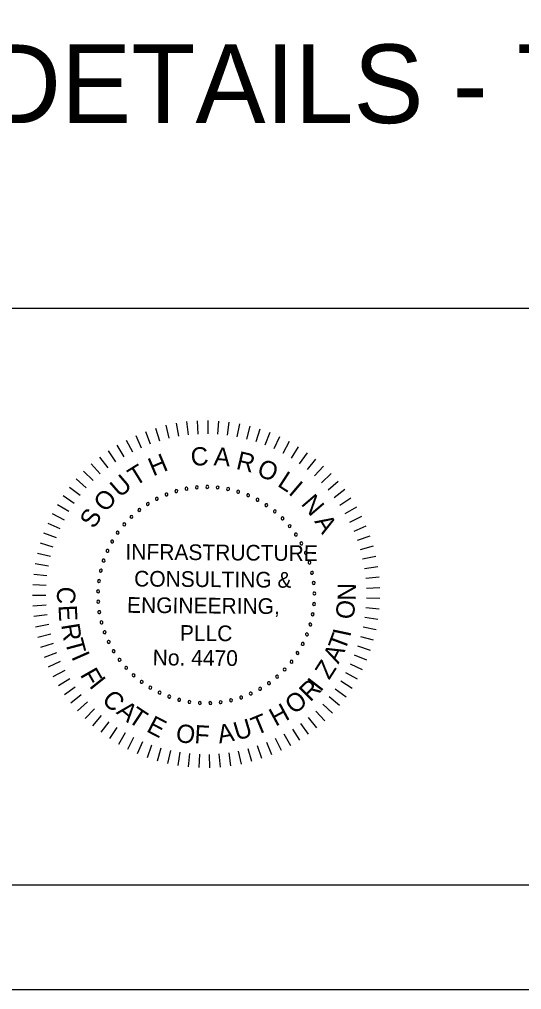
# Model space of a CAD drawing. Extents: x -125.5 to -89.4, y -5.1 to 16.9.
# Drawn here: x -100.09 to -97.697, y -5.066 to -0.44 of the extents above; entities that cross this region are included whole.
import ezdxf

# ---------------------------------------------------------------- set-up
doc = ezdxf.new("R2010")
doc.units = 0
for name, color, linetype in [('BR_BORDER LINES', 7, 'Continuous'), ('BR_TEXT', 7, 'Continuous'), ('Level 31', 7, 'Continuous')]:
    doc.layers.add(name, color=color, linetype=linetype)

msp = doc.modelspace()

# ---------------------------------------------------------------- linework, layer by layer
at = {"layer": 'BR_BORDER LINES'}
for p, q in [((-102.8989, -1.8161), (-97.5337, -1.8161)), ((-123.6994, -4.5662), (-90.0334, -4.5662))]:
    msp.add_line(p, q, dxfattribs=at)
at = {"layer": 'BR_TEXT'}
for p, q in [((-99.2931, -2.3579), (-99.2858, -2.4212)), ((-99.2427, -2.3538), (-99.2394, -2.4174)), ((-99.1923, -2.3527), (-99.1928, -2.4164)), ((-99.1418, -2.3548), (-99.1462, -2.4183)), ((-99.489, -2.4048), (-99.4667, -2.4644)), ((-99.4412, -2.3886), (-99.4226, -2.4495)), ((-99.3925, -2.3754), (-99.3776, -2.4373)), ((-99.343, -2.3651), (-99.332, -2.4278)), ((-99.0916, -2.3599), (-99.0999, -2.423)), ((-99.0418, -2.368), (-99.0539, -2.4305)), ((-98.9925, -2.3792), (-99.0084, -2.4408)), ((-98.9441, -2.3933), (-98.9637, -2.4539)), ((-99.5813, -2.4457), (-99.5519, -2.5022)), ((-99.5358, -2.4238), (-99.5099, -2.482)), ((-98.8966, -2.4104), (-98.9199, -2.4696)), ((-98.8502, -2.4303), (-98.877, -2.488)), ((-99.6678, -2.4975), (-99.6318, -2.55)), ((-99.6253, -2.4703), (-99.5926, -2.5249)), ((-98.8051, -2.453), (-98.8354, -2.509)), ((-98.7615, -2.4785), (-98.7952, -2.5325)), ((-99.7086, -2.5273), (-99.6694, -2.5775)), ((-98.7195, -2.5065), (-98.7564, -2.5584)), ((-98.6793, -2.5371), (-98.7193, -2.5866)), ((-99.7475, -2.5595), (-99.7053, -2.6072)), ((-98.6411, -2.57), (-98.684, -2.617)), ((-99.819, -2.6308), (-99.7713, -2.673)), ((-99.7843, -2.5941), (-99.7393, -2.6391)), ((-98.6049, -2.6052), (-98.6506, -2.6495)), ((-99.8513, -2.6695), (-99.8012, -2.7087)), ((-98.571, -2.6426), (-98.6193, -2.684)), ((-98.5393, -2.6819), (-98.5901, -2.7204)), ((-99.8813, -2.7102), (-99.8288, -2.7463)), ((-98.5102, -2.7232), (-98.5632, -2.7584)), ((-99.9087, -2.7526), (-99.8541, -2.7854)), ((-98.4836, -2.7661), (-98.5387, -2.798)), ((-99.9334, -2.7965), (-99.877, -2.826)), ((-98.4597, -2.8105), (-98.5166, -2.839)), ((-99.9555, -2.842), (-99.8973, -2.8679)), ((-98.4385, -2.8563), (-98.497, -2.8813)), ((-99.9747, -2.8886), (-99.9151, -2.911)), ((-98.4202, -2.9034), (-98.4801, -2.9248)), ((-99.991, -2.9364), (-99.9302, -2.9551)), ((-98.4047, -2.9514), (-98.4659, -2.9691)), ((-100.0044, -2.9851), (-99.9426, -3)), ((-98.3922, -3.0004), (-98.4544, -3.0143)), ((-100.0149, -3.0345), (-99.9522, -3.0456)), ((-98.3828, -3.05), (-98.4456, -3.0601)), ((-100.0222, -3.0844), (-99.959, -3.0917)), ((-100.0266, -3.1347), (-99.963, -3.1382)), ((-98.3763, -3.1), (-98.4397, -3.1063)), ((-100.0278, -3.1852), (-99.9641, -3.1847)), ((-98.373, -3.1504), (-98.4366, -3.1528)), ((-100.026, -3.2356), (-99.9625, -3.2313)), ((-98.3727, -3.2009), (-98.4363, -3.1994)), ((-100.0211, -3.2859), (-99.9579, -3.2777)), ((-98.3755, -3.2513), (-98.4389, -3.2459)), ((-100.0131, -3.3357), (-99.9506, -3.3237)), ((-98.3813, -3.3014), (-98.4443, -3.2922)), ((-100.0021, -3.385), (-99.9405, -3.3692)), ((-98.3902, -3.3511), (-98.4525, -3.3381)), ((-99.9882, -3.4335), (-99.9276, -3.414)), ((-98.4021, -3.4002), (-98.4635, -3.3834)), ((-99.9713, -3.4811), (-99.912, -3.4579)), ((-98.417, -3.4484), (-98.4773, -3.4279)), ((-99.9515, -3.5276), (-99.8937, -3.5008)), ((-98.4554, -3.5417), (-98.5128, -3.514)), ((-98.4348, -3.4957), (-98.4937, -3.4715)), ((-99.929, -3.5727), (-99.8729, -3.5425)), ((-98.4789, -3.5865), (-98.5344, -3.5553)), ((-99.9037, -3.6164), (-99.8496, -3.5828)), ((-98.505, -3.6297), (-98.5585, -3.5952)), ((-99.8758, -3.6585), (-99.8239, -3.6217)), ((-98.5336, -3.6712), (-98.5849, -3.6335)), ((-99.8454, -3.6988), (-99.7958, -3.6589)), ((-99.8126, -3.7372), (-99.7655, -3.6943)), ((-98.5648, -3.7109), (-98.6137, -3.6702)), ((-99.7775, -3.7735), (-99.7331, -3.7278)), ((-98.6341, -3.7843), (-98.6777, -3.7379)), ((-98.5983, -3.7487), (-98.6447, -3.705)), ((-99.7403, -3.8076), (-99.6988, -3.7593)), ((-99.701, -3.8393), (-99.6626, -3.7886)), ((-98.672, -3.8177), (-98.7126, -3.7687)), ((-99.6599, -3.8687), (-99.6246, -3.8157)), ((-98.7534, -3.8772), (-98.7879, -3.8237)), ((-98.7118, -3.8487), (-98.7494, -3.7974)), ((-99.6171, -3.8954), (-99.5851, -3.8404)), ((-99.5728, -3.9195), (-99.5442, -3.8626)), ((-99.527, -3.9408), (-99.5019, -3.8823)), ((-98.8416, -3.9264), (-98.8692, -3.8691)), ((-98.7967, -3.9032), (-98.8278, -3.8476)), ((-99.48, -3.9594), (-99.4586, -3.8994)), ((-99.432, -3.975), (-99.4143, -3.9138)), ((-99.3832, -3.9876), (-99.3692, -3.9255)), ((-99.0324, -3.991), (-99.0454, -3.9286)), ((-98.9833, -3.9792), (-99.0001, -3.9178)), ((-98.935, -3.9645), (-98.9555, -3.9042)), ((-98.8877, -3.9469), (-98.9118, -3.888)), ((-99.3336, -3.9973), (-99.3234, -3.9344)), ((-99.2836, -4.0039), (-99.2772, -3.9406)), ((-99.2332, -4.0075), (-99.2307, -3.9438)), ((-99.1827, -4.0079), (-99.1841, -3.9443)), ((-99.1323, -4.0053), (-99.1376, -3.9419)), ((-99.0821, -3.9997), (-99.0913, -3.9367))]:
    msp.add_line(p, q, dxfattribs=at)
for centre, start, end in [((-99.3424, -2.6889), 16.1422, 196.1422), ((-99.2939, -2.6775), 10.6038, 190.6038), ((-99.2939, -2.6775), 190.6038, 10.6038), ((-99.2445, -2.6708), 5.0653, 185.0653), ((-99.2445, -2.6708), 185.0653, 5.0653), ((-99.1947, -2.6689), 359.5268, 179.5268), ((-99.1947, -2.6689), 179.5268, 359.5268), ((-99.145, -2.6718), 173.9884, 353.9884), ((-99.145, -2.6718), 353.9884, 173.9884), ((-99.0957, -2.6795), 168.4499, 348.4499), ((-99.0957, -2.6795), 348.4499, 168.4499), ((-99.435, -2.7255), 27.2191, 207.2191), ((-99.435, -2.7255), 207.2191, 27.2191), ((-99.3896, -2.705), 21.6807, 201.6807), ((-99.3896, -2.705), 201.6807, 21.6807), ((-99.3424, -2.6889), 196.1422, 16.1422), ((-99.0475, -2.6919), 162.9114, 342.9114), ((-99.0475, -2.6919), 342.9114, 162.9114), ((-99.0006, -2.709), 157.373, 337.373), ((-99.0006, -2.709), 337.373, 157.373), ((-98.9557, -2.7304), 151.8345, 331.8345), ((-98.9557, -2.7304), 331.8345, 151.8345), ((-99.5188, -2.7792), 38.2961, 218.2961), ((-99.5188, -2.7792), 218.2961, 38.2961), ((-99.4782, -2.7503), 32.7576, 212.7576), ((-99.4782, -2.7503), 212.7576, 32.7576), ((-98.913, -2.7561), 146.2961, 326.2961), ((-98.913, -2.7561), 326.2961, 146.2961), ((-99.5564, -2.8119), 43.8345, 223.8345), ((-99.5564, -2.8119), 223.8345, 43.8345), ((-98.873, -2.7858), 140.7576, 320.7576), ((-98.873, -2.7858), 320.7576, 140.7576), ((-98.836, -2.8192), 135.2191, 315.2191), ((-98.836, -2.8192), 315.2191, 135.2191), ((-99.5907, -2.848), 49.373, 229.373), ((-99.5907, -2.848), 229.373, 49.373), ((-98.8024, -2.8561), 129.6807, 309.6807), ((-98.8024, -2.8561), 309.6807, 129.6807), ((-99.6214, -2.8873), 54.9114, 234.9114), ((-99.6214, -2.8873), 234.9114, 54.9114), ((-98.7726, -2.896), 124.1422, 304.1422), ((-98.7726, -2.896), 304.1422, 124.1422), ((-99.6481, -2.9293), 60.4499, 240.4499), ((-99.6481, -2.9293), 240.4499, 60.4499), ((-98.7467, -2.9386), 118.6038, 298.6038), ((-98.7467, -2.9386), 298.6038, 118.6038), ((-99.6706, -2.9738), 65.9884, 245.9884), ((-99.6706, -2.9738), 245.9884, 65.9884), ((-98.7251, -2.9835), 113.0653, 293.0653), ((-98.7251, -2.9835), 293.0653, 113.0653), ((-99.6888, -3.0202), 71.5268, 251.5268), ((-99.6888, -3.0202), 251.5268, 71.5268), ((-98.7079, -3.0302), 107.5268, 287.5268), ((-98.7079, -3.0302), 287.5268, 107.5268), ((-99.7024, -3.0681), 77.0653, 257.0653), ((-99.7024, -3.0681), 257.0653, 77.0653), ((-98.6953, -3.0785), 101.9884, 281.9884), ((-98.6953, -3.0785), 281.9884, 101.9884), ((-99.7113, -3.1172), 82.6038, 262.6038), ((-99.7113, -3.1172), 262.6038, 82.6038), ((-98.6874, -3.1277), 96.4499, 276.4499), ((-98.6874, -3.1277), 276.4499, 96.4499), ((-99.7154, -3.1668), 88.1422, 268.1422), ((-99.7154, -3.1668), 268.1422, 88.1422), ((-98.6843, -3.1774), 90.9114, 270.9114), ((-98.6843, -3.1774), 270.9114, 90.9114), ((-99.7147, -3.2167), 93.6807, 273.6807), ((-99.7147, -3.2167), 273.6807, 93.6807), ((-98.686, -3.2272), 85.373, 265.373), ((-98.686, -3.2272), 265.373, 85.373), ((-99.7092, -3.2662), 99.2191, 279.2191), ((-99.7092, -3.2662), 279.2191, 99.2191), ((-98.6926, -3.2766), 79.8345, 259.8345), ((-98.6926, -3.2766), 259.8345, 79.8345), ((-99.6989, -3.3149), 104.7576, 284.7576), ((-99.6989, -3.3149), 284.7576, 104.7576), ((-98.7038, -3.3251), 74.2961, 254.2961), ((-98.7038, -3.3251), 254.2961, 74.2961), ((-99.684, -3.3625), 110.2961, 290.2961), ((-99.684, -3.3625), 290.2961, 110.2961), ((-98.7197, -3.3724), 68.7576, 248.7576), ((-98.7197, -3.3724), 248.7576, 68.7576), ((-99.6646, -3.4084), 115.8345, 295.8345), ((-99.6646, -3.4084), 295.8345, 115.8345), ((-98.7401, -3.4178), 63.2191, 243.2191), ((-98.7401, -3.4178), 243.2191, 63.2191), ((-99.6408, -3.4522), 121.373, 301.373), ((-99.6408, -3.4522), 301.373, 121.373), ((-98.7647, -3.4611), 57.6807, 237.6807), ((-98.7647, -3.4611), 237.6807, 57.6807), ((-99.6129, -3.4935), 126.9114, 306.9114), ((-99.6129, -3.4935), 306.9114, 126.9114), ((-98.7934, -3.5019), 52.1422, 232.1422), ((-98.7934, -3.5019), 232.1422, 52.1422), ((-99.5812, -3.5319), 132.4499, 312.4499), ((-99.5812, -3.5319), 312.4499, 132.4499), ((-99.5459, -3.5671), 317.9884, 137.9884), ((-98.826, -3.5396), 46.6038, 226.6038), ((-98.826, -3.5396), 226.6038, 46.6038), ((-99.5459, -3.5671), 137.9884, 317.9884), ((-99.5074, -3.5987), 143.5268, 323.5268), ((-99.5074, -3.5987), 323.5268, 143.5268), ((-98.9012, -3.6049), 35.5268, 215.5268), ((-98.9012, -3.6049), 215.5268, 35.5268), ((-98.862, -3.5741), 41.0653, 221.0653), ((-98.862, -3.5741), 221.0653, 41.0653), ((-99.466, -3.6264), 149.0653, 329.0653), ((-99.466, -3.6264), 329.0653, 149.0653), ((-99.4221, -3.65), 154.6038, 334.6038), ((-99.4221, -3.65), 334.6038, 154.6038), ((-98.9875, -3.6545), 24.4499, 204.4499), ((-98.9875, -3.6545), 204.4499, 24.4499), ((-98.9431, -3.6317), 29.9884, 209.9884), ((-98.9431, -3.6317), 209.9884, 29.9884), ((-99.3761, -3.6693), 160.1422, 340.1422), ((-99.3761, -3.6693), 340.1422, 160.1422), ((-99.3285, -3.684), 165.6807, 345.6807), ((-99.3285, -3.684), 345.6807, 165.6807), ((-99.2797, -3.6941), 351.2191, 171.2191), ((-99.2797, -3.6941), 171.2191, 351.2191), ((-99.2302, -3.6994), 356.7576, 176.7576), ((-99.2302, -3.6994), 176.7576, 356.7576), ((-99.1803, -3.6999), 2.2961, 182.2961), ((-99.1803, -3.6999), 182.2961, 2.2961), ((-99.1307, -3.6956), 7.8345, 187.8345), ((-99.1307, -3.6956), 187.8345, 7.8345), ((-99.0817, -3.6865), 13.373, 193.373), ((-99.0817, -3.6865), 193.373, 13.373), ((-99.0338, -3.6728), 18.9114, 198.9114), ((-99.0338, -3.6728), 198.9114, 18.9114)]:
    msp.add_arc(centre, 0.00701, start, end, dxfattribs=at)
at = {"layer": 'Level 31'}
msp.add_lwpolyline([(-125.5328, -5.0661), (-89.5328, -5.0661), (-89.5328, 16.9339), (-125.5328, 16.9339)], close=True, dxfattribs=at)

# ---------------------------------------------------------------- texts
at = {"layer": 'BR_TEXT'}
msp.add_text('BEARING PAD DETAILS - TYPE 2', height=0.375, dxfattribs=at).set_placement((-103.821, -0.9342))
for s, height, rotation, p in [('C', 0.0872, 4.7281, (-99.2702, -2.5703)), ('A', 0.0872, 355.6981, (-99.1657, -2.5654)), ('H', 0.0872, 22.7882, (-99.453, -2.6197)), ('R', 0.0872, 346.6681, (-99.0615, -2.5824)), ('O', 0.0872, 337.638, (-98.9637, -2.6122)), ('T', 0.0872, 31.8182, (-99.5379, -2.6674)), ('U', 0.0872, 40.8482, (-99.6112, -2.7235)), ('L', 0.0872, 327.108, (-98.8649, -2.6626)), ('I', 0.0872, 319.578, (-98.8123, -2.7005)), ('O', 0.0872, 49.8782, (-99.6782, -2.7945)), ('N', 0.0872, 310.548, (-98.7515, -2.7512)), ('S', 0.0872, 58.9083, (-99.7336, -2.8727)), ('A', 0.0872, 301.5179, (-98.6864, -2.8336)), ('INFRASTRUCTURE', 0.074771, 359.5268, (-99.585, -3.0152)), ('CONSULTING &', 0.074771, 359.5268, (-99.5437, -3.1438)), ('N', 0.0872, 89.2085, (-98.4872, -3.2124)), ('C', 0.0872, 267.025, (-99.9086, -3.1426)), ('ENGINEERING,', 0.074771, 359.5268, (-99.5773, -3.2693)), ('O', 0.0872, 83.2085, (-98.4982, -3.3038)), ('E', 0.0872, 273.025, (-99.9042, -3.2342)), ('R', 0.0872, 279.025, (-99.8914, -3.3265)), ('PLLC', 0.07477, 359.5268, (-99.3256, -3.4028)), ('T', 0.0872, 69.3954, (-98.5394, -3.4556)), ('I', 0.0872, 77.9093, (-98.5137, -3.3881)), ('T', 0.0872, 285.025, (-99.874, -3.4053)), ('I', 0.0872, 293.7713, (-99.8443, -3.4784)), ('No. 4470', 0.07477, 359.5268, (-99.4551, -3.5197)), ('A', 0.0872, 63.3954, (-98.5702, -3.516)), ('Z', 0.0872, 57.3954, (-98.6141, -3.5923)), ('F', 0.0872, 299.7713, (-99.8031, -3.5644)), ('I', 0.0872, 308.5268, (-99.761, -3.6183)), ('R', 0.0872, 44.5268, (-98.7045, -3.6973)), ('I', 0.0872, 52.3339, (-98.6551, -3.65)), ('C', 0.0872, 314.5268, (-99.7017, -3.6884)), ('O', 0.0872, 38.5268, (-98.7811, -3.7572)), ('A', 0.0872, 320.5268, (-99.6325, -3.747)), ('H', 0.0872, 28.5268, (-98.8692, -3.8132)), ('T', 0.0872, 326.5268, (-99.5781, -3.7855)), ('E', 0.0872, 332.5268, (-99.4895, -3.8332)), ('U', 0.0872, 16.5268, (-99.0541, -3.8794)), ('T', 0.0872, 22.5268, (-98.9624, -3.855)), ('O', 0.0872, 350.5268, (-99.3494, -3.8821)), ('F', 0.0872, 356.5268, (-99.2579, -3.8912)), ('A', 0.0872, 10.5268, (-99.138, -3.8929))]:
    msp.add_text(s, height=height, rotation=rotation, dxfattribs=at).set_placement(p)

doc.saveas('drawing.dxf')
